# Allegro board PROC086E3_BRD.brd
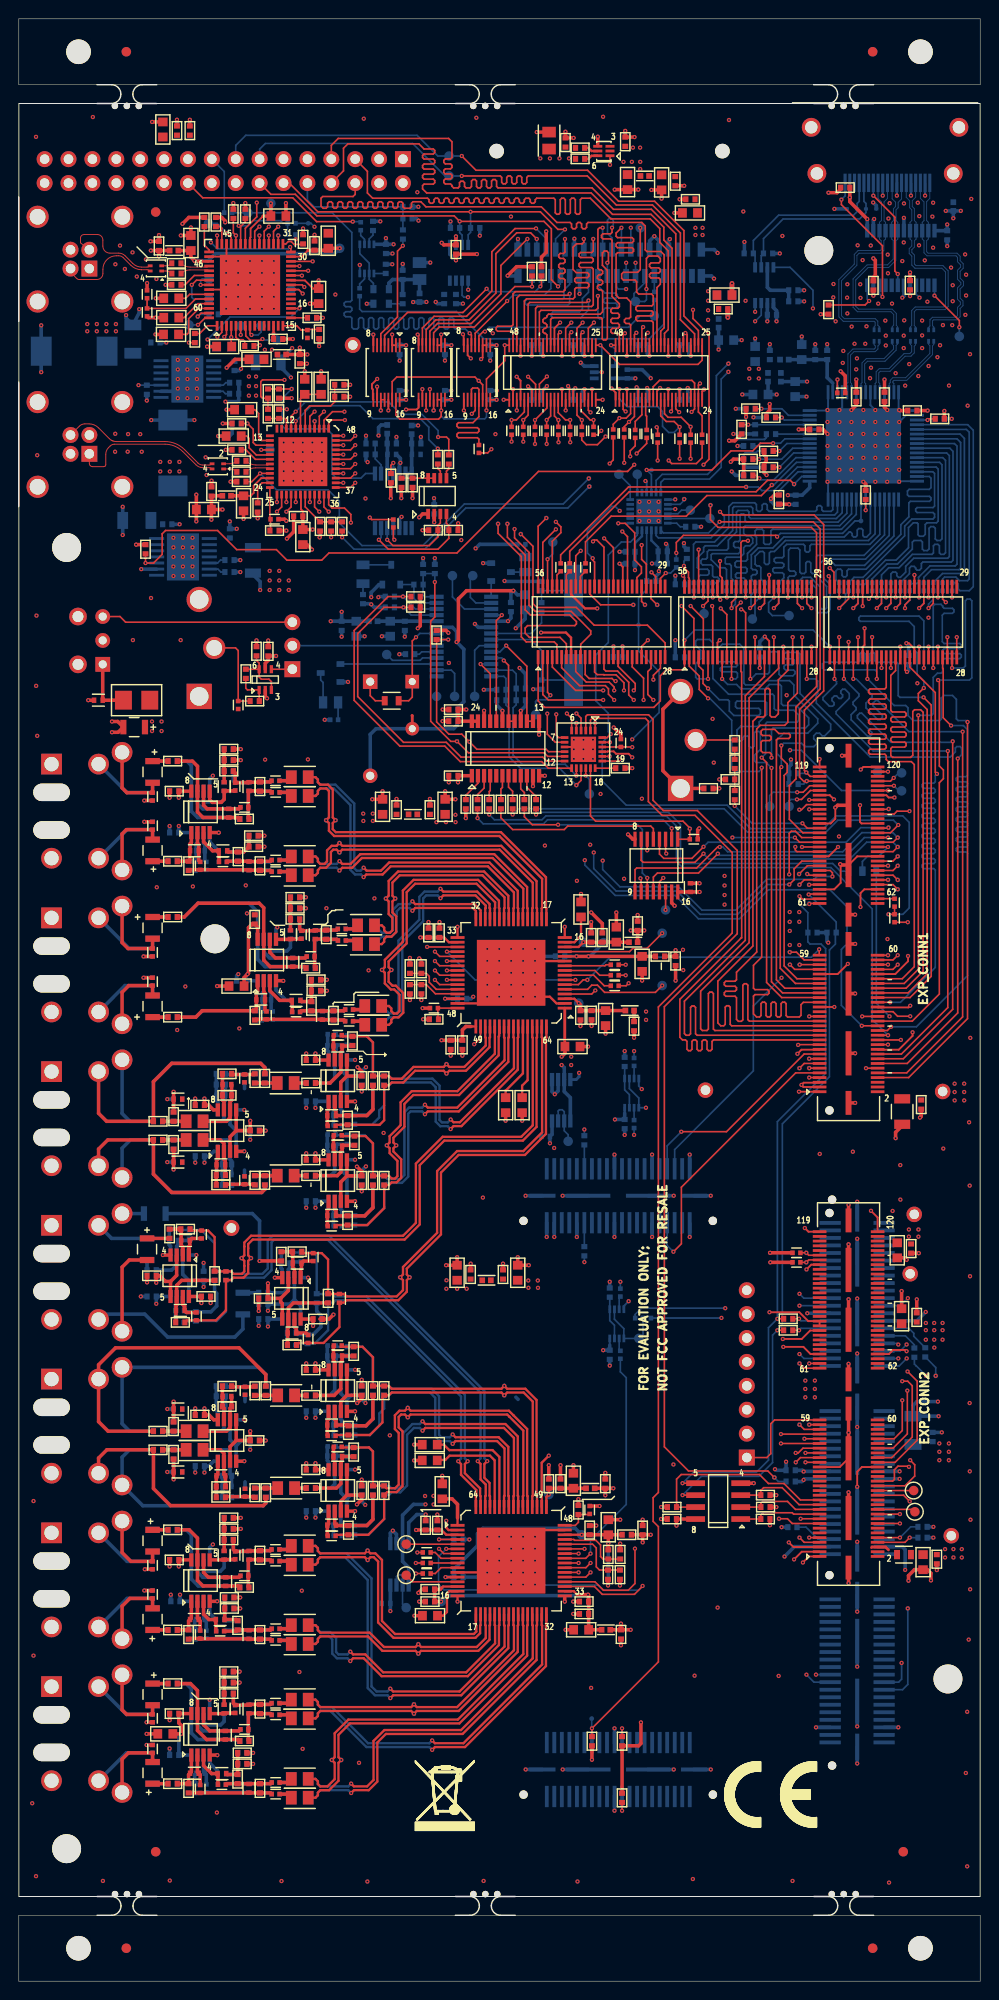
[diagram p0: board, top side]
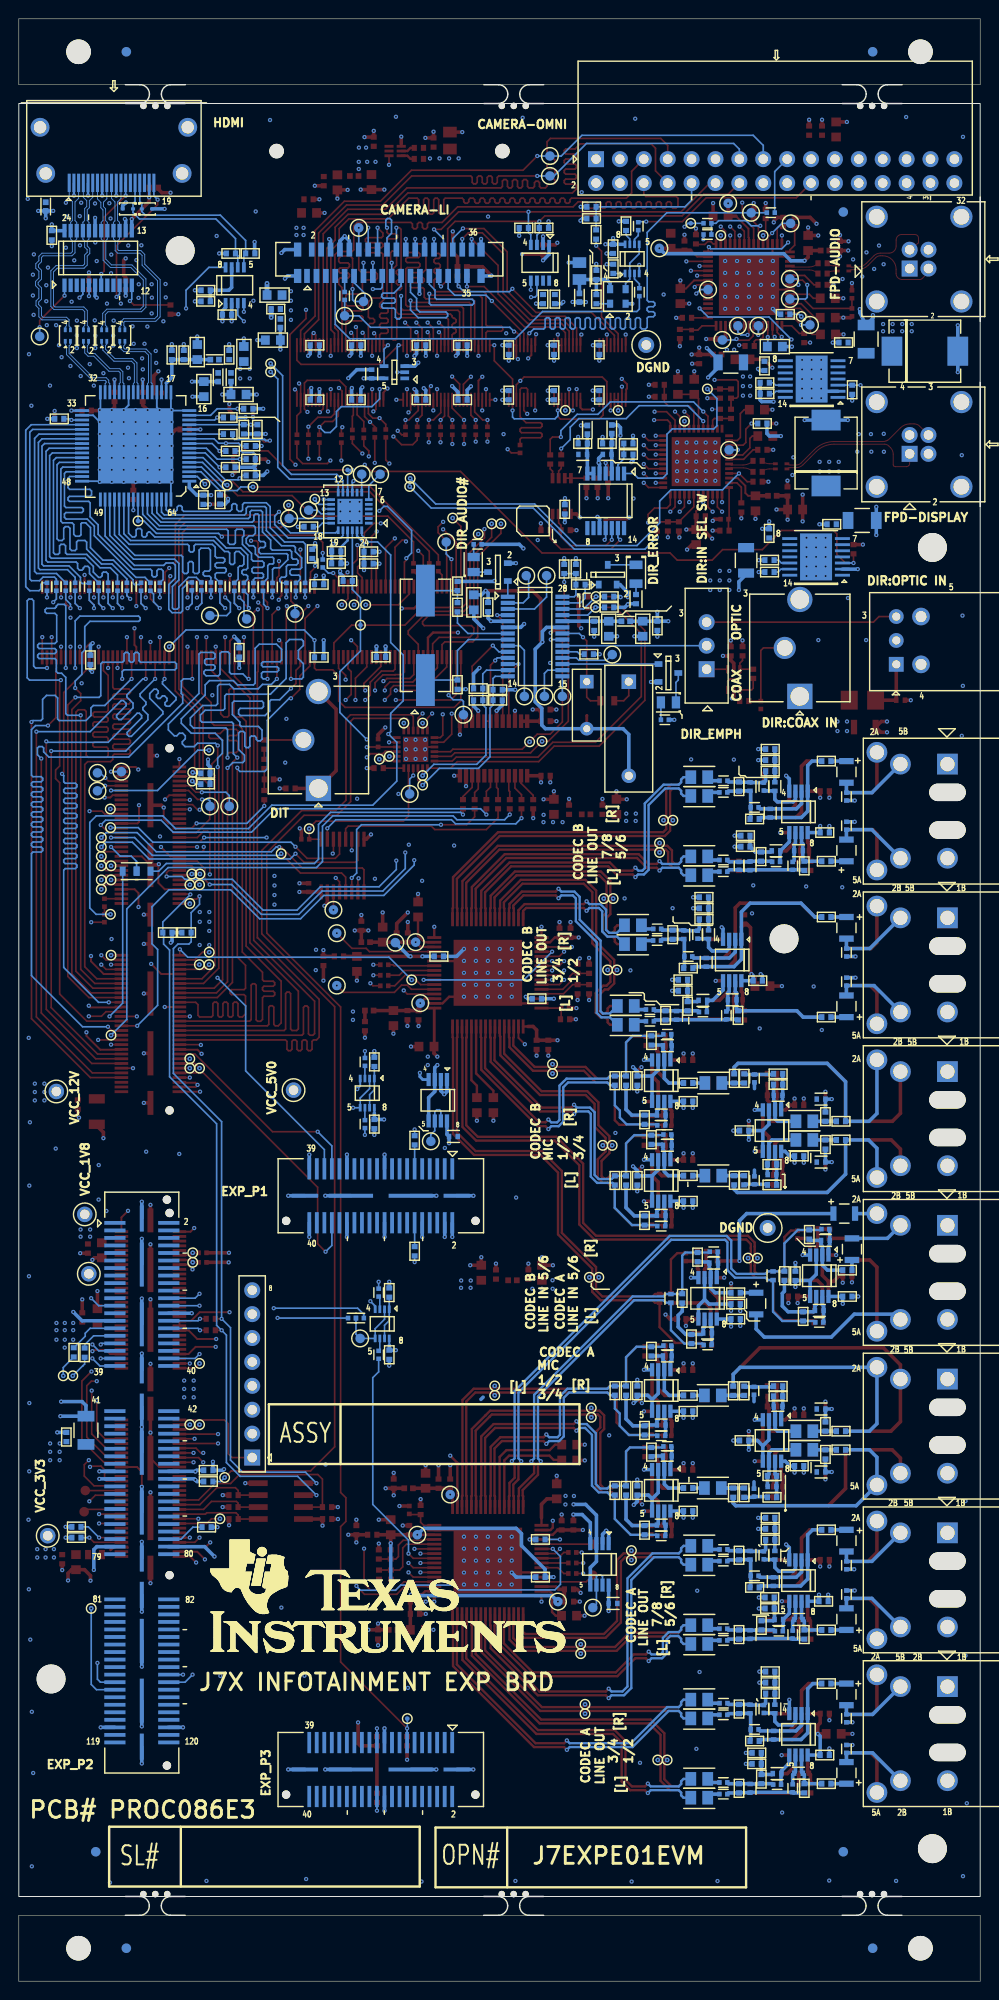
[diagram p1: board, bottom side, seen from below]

Outline 102.21 x 208.5 mm; copper layers: TOP, L02_GND1, L03_SIG1, L04_GND2, L05_PWR1, L06_PWR2, L07_GND3, L08_SIG2, L09_GND4, BOTTOM. Coordinates in mm from the lower left corner of the outline.
Outline path: rectangle 0,9 102.21,199.5 ; 0,208.5 0,201.5 102.21,201.5 102.21,208.5 0,208.5 ; 0,7 0,0 102.21,0 102.21,7 0,7

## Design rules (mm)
net group BUF_VPFE0_DATA0: nets BUF_VPFE0_DATA0 VPFE0_DATA0
net group BUF_VPFE0_DATA1: nets BUF_VPFE0_DATA1 VPFE0_DATA1
net group BUF_VPFE0_DATA2: nets BUF_VPFE0_DATA2 VPFE0_DATA2
net group BUF_VPFE0_DATA3: nets BUF_VPFE0_DATA3 VPFE0_DATA3
net group BUF_VPFE0_DATA4: nets BUF_VPFE0_DATA4 VPFE0_DATA4
net group BUF_VPFE0_DATA5: nets BUF_VPFE0_DATA5 VPFE0_DATA5
net group BUF_VPFE0_DATA6: nets BUF_VPFE0_DATA6 VPFE0_DATA6
net group BUF_VPFE0_DATA7: nets BUF_VPFE0_DATA7 VPFE0_DATA7
net group BUF_VPFE0_DATA8: nets BUF_VPFE0_DATA8 VPFE0_DATA8
net group BUF_VPFE0_DATA9: nets BUF_VPFE0_DATA9 VPFE0_DATA9
net group BUF_VPFE0_DATA10: nets BUF_VPFE0_DATA10 VPFE0_DATA10
net group BUF_VPFE0_DATA11: nets BUF_VPFE0_DATA11 VPFE0_DATA11
net group BUF_VPFE0_DATA12: nets BUF_VPFE0_DATA12 VPFE0_DATA12
net group BUF_VPFE0_DATA13: nets BUF_VPFE0_DATA13 VPFE0_DATA13
net group BUF_VPFE0_HD: nets BUF_VPFE0_HD VPFE0_HD
net group BUF_VPFE0_PCLK: nets BUF_VPFE0_PCLK VPFE0_PCLK
net group BUF_VPFE0_VD: nets BUF_VPFE0_VD VPFE0_VD
net group DIFFPAIR0: nets AOUT2_N AOUT2_P
net group DIFFPAIR1: nets AOUT1_N AOUT1_P
net group DIFFPAIR2: nets AOUT6_N AOUT6_P
net group DIFFPAIR3: nets AOUT5_N AOUT5_P
net group DIFFPAIR4: nets AOUT3_N AOUT3_P
net group DIFFPAIR5: nets AOUT4_N AOUT4_P
net group DIFFPAIR6: nets AOUT7_N AOUT7_P
net group DIFFPAIR7: nets AOUT8_N AOUT8_P
net group DIFFPAIR8: nets AIN4_N AIN4_P
net group DIFFPAIR9: nets AIN3_N AIN3_P
net group DIFFPAIR10: nets AIN2_N AIN2_P
net group DIFFPAIR11: nets AIN1_N AIN1_P
net group DIFFPAIR12: nets AIN6_N AIN6_P
net group DIFFPAIR14: nets AIN5_N AIN5_P
net group DIFFPAIR15: nets BOUT2_N BOUT2_P
net group DIFFPAIR16: nets BOUT1_N BOUT1_P
net group DIFFPAIR17: nets BOUT6_N BOUT6_P
net group DIFFPAIR18: nets BOUT5_N BOUT5_P
net group DIFFPAIR19: nets BOUT3_N BOUT3_P
net group DIFFPAIR20: nets BOUT4_N BOUT4_P
net group DIFFPAIR21: nets BOUT7_N BOUT7_P
net group DIFFPAIR22: nets BOUT8_N BOUT8_P
net group DIFFPAIR24: nets BIN1_N BIN1_P
net group DIFFPAIR25: nets BIN2_N BIN2_P
net group DIFFPAIR27: nets BIN4_N BIN4_P
net group DIFFPAIR36: nets C_FPD_RIN_N C_FPD_RIN_P
net group DIFFPAIR37: nets CMC_FPD_RIN_N CMC_FPD_RIN_P
net group DIFFPAIR38: nets FPD_RIN_N FPD_RIN_P
net group DIFFPAIR39: nets C_FPD_DOUT_N C_FPD_DOUT_P
net group DIFFPAIR40: nets CMC_FPD_DOUT_N CMC_FPD_DOUT_P
net group DIFFPAIR41: nets FPD_DOUT_N FPD_DOUT_P
net group DIFFPAIR45: nets BIN6_N BIN6_P
net group DIFFPAIR46: nets BIN5_N BIN5_P
net group DIFFPAIR47: nets BIN3_N BIN3_P
net group HDMI1_DATA0: nets HDMI1_DATA0 HDMI1_DATA0_R
net group HDMI1_DATA1: nets HDMI1_DATA1 HDMI1_DATA1_R
net group HDMI1_DATA2: nets HDMI1_DATA2 HDMI1_DATA2_R
net group HDMI1_DATA3: nets HDMI1_DATA3 HDMI1_DATA3_R
net group HDMI1_DATA4: nets HDMI1_DATA4 HDMI1_DATA4_R
net group HDMI1_DATA5: nets HDMI1_DATA5 HDMI1_DATA5_R
net group HDMI1_DATA6: nets HDMI1_DATA6 HDMI1_DATA6_R
net group HDMI1_DATA7: nets HDMI1_DATA7 HDMI1_DATA7_R
net group HDMI1_DATA8: nets HDMI1_DATA8 HDMI1_DATA8_R
net group HDMI1_DATA9: nets HDMI1_DATA9 HDMI1_DATA9_R
net group HDMI1_DATA10: nets HDMI1_DATA10 HDMI1_DATA10_R
net group HDMI1_DATA11: nets HDMI1_DATA11 HDMI1_DATA11_R
net group HDMI1_DATA12: nets HDMI1_DATA12 HDMI1_DATA12_R
net group HDMI1_DATA13: nets HDMI1_DATA13 HDMI1_DATA13_R
net group HDMI1_DATA14: nets HDMI1_DATA14 HDMI1_DATA14_R
net group HDMI1_DATA15: nets HDMI1_DATA15 HDMI1_DATA15_R
net group HDMI1_DATA16: nets HDMI1_DATA16 HDMI1_DATA16_R
net group HDMI1_DATA17: nets HDMI1_DATA17 HDMI1_DATA17_R
net group HDMI1_DATA18: nets HDMI1_DATA18 HDMI1_DATA18_R
net group HDMI1_DATA19: nets HDMI1_DATA19 HDMI1_DATA19_R
net group HDMI1_DATA20: nets HDMI1_DATA20 HDMI1_DATA20_R
net group HDMI1_DATA21: nets HDMI1_DATA21 HDMI1_DATA21_R
net group HDMI1_DATA22: nets HDMI1_DATA22 HDMI1_DATA22_R
net group HDMI1_DATA23: nets HDMI1_DATA23 HDMI1_DATA23_R
net group HDMI1_DE: nets HDMI1_DE HDMI1_DE_R
net group HDMI1_HSYNC: nets HDMI1_HSYNC HDMI1_HSYNC_R
net group HDMI1_PCLK: nets HDMI1_PCLK HDMI1_PCLK_R
net group HDMI1_VSYNC: nets HDMI1_VSYNC HDMI1_VSYNC_R
net group LI_VIN_PCLK: nets LI_VIN_PCLK R_LI_VIN_PCLK
net group MCASP0_AXR12: nets MCASP0_AXR12 MCASP0_AXR12_R
net group MCASP0_AXR13: nets MCASP0_AXR13 MCASP0_AXR13_R
net group OV_VIN_PCLK_R: nets OV_VIN_PCLK OV_VIN_PCLK_R
net group CAMERA: nets LI_VIN_DATA3 LI_VIN_DATA4 LI_VIN_DATA5 LI_VIN_DATA6 LI_VIN_DATA7 LI_VIN_DATA8 LI_VIN_DATA9 LI_VIN_DATA10 LI_VIN_DATA11 LI_VIN_DATA12 LI_VIN_DATA13
net group MCASP0-GP1: nets MCASP0_AXR7 MCASP0_AXR8 MCASP0_AXR9
net group MCASP0_AXR4: nets MCASP0_AXR4_R
net group MCASP0_AXR5: nets MCASP0_AXR5_R
net group MCASP0_AXR6: nets MCASP0_AXR6_R
net group MCASP0_AXR11: nets MCASP0_AXR11
net group MCASP1: nets MCASP1_ACLKX MCASP1_AFSX MCASP1_AXR0 MCASP1_AXR1 MCASP1_AXR2 MCASP1_AXR3 MCASP1_AXR5 MCASP1_AXR7 MCASP1_AXR8
net group OV_VIN_D0-D11: nets OV_VIN_VD
net group PCLK_R: nets FPD_PCLK
net group POWER: nets DIT_GND N24788879 V3V3_OPTICAL V5V0_HDMI1_CONN V_PVDD VCC_CAM_OSC VCC_DIR VCOMDA1 VCOMDA2 VDD33_FPD VDD33_UB926 VDD_CDCE VDDOUT_CDCE VLDO_CAM_1V8 VLDO_CAM_3V3
net group VOUT0_DATA0_M1: nets VOUT0_DE VOUT0_HSYNC VOUT0_VSYNC

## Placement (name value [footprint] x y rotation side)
C1  2.2uF  [CAP0805_1-5]  56.38 195.56 90 top
C2  1uF  [CAP0402_0-5]  64.47 195.44 90 top
C3  10uF  [CAP0603_1]  68.34 191.12 270 top
C4  10uF  [CAP0603_1]  64.72 191.16 270 top
C5  0.1uF  [CAP0402_0-75]  69.79 191.25 270 top
C6  0.1uF  [CAP0402_0-75]  87.86 190.57 180 top
C7  0.1uF  [CAP0402_0-75]  71.4 189.33 180 top
C8  0.1uF  [CAP0402_0-75]  27.57 174.48 0 top
C9  4.7uF  [CAP0603_1]  27.6 187.54 0 top
C10  10uF  [CAP0603_1]  71.35 187.88 180 top
C11  4.7uF  [CAP0603_1]  32.9 184.92 90 top
C12  4.7uF  [CAP0603_1]  18.3 184.68 90 top
C13  0.1uF  [CAP0402_0-75]  31.44 184.41 90 top
C14  0.1uF  [CAP0402_0-75]  14.91 184.37 90 top
C15  0.1uF  [CAP0402_0-75]  46.48 183.99 270 top
C16  0.1uF  [CAP0402_0-75]  16.75 182.53 180 top
C17  0.1uF  [CAP0402_0-75]  16.76 181.44 180 top
C18  0.1uF  [CAP0402_0-75]  16.76 180.24 180 top
C19  10uF  [CAP0603_1]  75.02 179.15 0 top
C20  4.7uF  [CAP0603_1]  31.88 179.04 270 top
C21  4.7uF  [CAP0603_1]  16.21 178.81 180 top
C22  0.1uF  [CAP0402_0-75]  74.89 177.66 0 top
C23  4.7uF  [CAP0603_1]  16.21 176.75 180 top
C24  4.7uF  [CAP0603_1]  16.18 174.97 180 top
C25  4.7uF  [CAP0603_1]  25.27 172.32 180 top
C26  4.7uF  [CAP0603_1]  21.83 173.68 180 top
C27  0.1uF  [CAP0402_0-75]  29.88 172.35 270 top
C28  4.7uF  [CAP0603_1]  30.4 169.4 90 top
C29  4.7uF  [CAP0603_1]  32.14 169.4 90 top
C30  0.1uF  [CAP0402_0-75]  89.04 168.33 270 top
C31  0.1uF  [CAP0402_0-75]  92.04 168.33 270 top
C32  4.7uF  [CAP0603_1]  23.74 166.97 180 top
C33  0.1uF  [CAP0402_0-75]  95 166.87 180 top
C34  0.1uF  [CAP0402_0-75]  84.58 164.87 0 top
C35  4.7uF  [CAP0603_1]  22.85 164.17 180 top
C36  0.1uF  [CAP0402_0-75]  23.66 161.53 180 top
C37  0.1uF  [CAP0402_0-75]  23.66 160.37 180 top
C38  0.1uF  [CAP0402_0-75]  41.86 159.2 270 top
C39  10uF  [CAP0603_1]  19.68 156.36 180 top
C40  0.1uF  [CAP0402_0-75]  20.49 158.28 90 top
C41  10uF  [CAP0603_1]  23.89 157.02 270 top
C42  0.1uF  [CAP0402_0-75]  25.4 156.58 90 top
C43  0.1uF  [CAP0402_0-75]  29.71 155.65 180 top
C44  10uF  [CAP0603_1]  30.2 153.44 270 top
C45  0.1uF  [CAP0402_0-75]  26.52 141.3 90 top
C46  0.1uF  [CAP0402_0-75]  8.46 136.1 180 top
C47  0.1uF  [CAP0402_0-75]  25.08 136.01 180 top
C48  0.1uF  [CAP0402_0-75]  46.21 135.11 180 top
C49  0.1uF  [CAP0402_0-75]  46.2 133.88 180 top
C50  10uF_10V  [CAPCT0805H_1]  12.26 133.25 180 top
C51  0.1uF  [CAP0402_0-75]  76.11 129.33 90 top
C52  10uF_10V  [CAPCT0805H_1]  14.22 128.48 270 top
C53  680pF  [CAP0402_0-75]  22.32 124.1 270 top
C54  0.1uF  [CAP0402_0-75]  46.2 128.08 180 top
C55  10uF  [CAP0805_1-5]  29.87 127.93 0 top
C56  680pF  [CAP0402_0-75]  21.83 126.93 90 top
C57  3300pF  [CAP0402_0-75]  24.47 126.93 90 top
C58  0.1uF  [CAP0402_0-75]  16.52 126.44 180 top
C59  10uF  [CAP0805_1-5]  29.87 125.93 0 top
C60  10uF  [CAP0603_1]  38.67 124.78 90 top
C61  10uF  [CAP0603_1]  45.32 124.78 90 top
C62  0.1uF  [CAP0402_0-75]  40.16 124.47 90 top
C63  0.1uF  [CAP0402_0-75]  43.71 124.47 90 top
C64  10uF_10V  [CAPCT0805H_1]  14.22 120.14 90 top
C65  680pF  [CAP0402_0-75]  18.67 120.11 180 top
C66  10uF  [CAP0805_1-5]  29.87 119.5 0 top
C67  680pF  [CAP0402_0-75]  21.7 120.1 0 top
C68  3300pF  [CAP0402_0-75]  24.47 118.5 90 top
C69  10uF  [CAP0805_1-5]  29.87 117.51 0 top
C70  0.1uF  [CAP0402_0-75]  71.4 116.19 90 top
C71  680pF  [CAP0402_0-75]  29.13 108.25 270 top
C72  10uF_10V  [CAPCT0805H_1]  14.22 111.92 270 top
C73  10uF  [CAP0805_1-5]  36.92 112.19 0 top
C74  10uF  [CAP0603_1]  59.77 113.87 90 top
C75  680pF  [CAP0402_0-75]  28.88 111.19 90 top
C76  3300pF  [CAP0402_0-75]  31.52 111.19 90 top
C77  0.1uF  [CAP0402_0-75]  65.79 112.13 90 top
C78  0.1uF  [CAP0402_0-75]  25.08 112.81 90 top
C79  0.1uF  [CAP0402_0-75]  43.56 111.38 90 top
C80  1uF  [CAP0402_0-5]  44.72 111.38 90 top
C81  10uF  [CAP0805_1-5]  36.92 110.19 0 top
C82  10uF  [CAP0603_1]  63.53 111.19 90 top
C83  0.1uF  [CAP0402_0-75]  60.85 110.88 90 top
C84  1uF  [CAP0402_0-5]  62.03 110.88 90 top
C85  10uF  [CAP0603_1]  23.15 105.73 180 top
C86  0.1uF  [CAP0402_0-75]  69.83 108.4 270 top
C87  10uF  [CAP0603_1]  66.27 108.09 270 top
C88  680pF  [CAP0402_0-75]  25.72 104.27 180 top
C89  10uF_10V  [CAPCT0805H_1]  14.22 103.58 90 top
C90  10uF  [CAP0805_1-5]  37.68 103.61 0 top
C91  680pF  [CAP0402_0-75]  29.48 104.21 0 top
C92  3300pF  [CAP0402_0-75]  32.28 102.61 90 top
C93  1uF  [CAP0402_0-5]  60.89 102.64 270 top
C94  1uF  [CAP0402_0-5]  59.71 102.63 270 top
C95  10uF  [CAP0603_1]  62.38 102.33 270 top
C96  10uF  [CAP0805_1-5]  37.68 101.62 0 top
C97  0.1uF  [CAP0402_0-75]  65.41 101.47 270 top
C98  2200pF  [CAP0402_0-75]  33.91 99.36 180 top
C99  0.1uF  [CAP0402_0-75]  31.05 97.87 180 top
C100  10uF  [CAP0603_1]  58.87 99.3 0 top
C101  0.1uF  [CAP0402_0-75]  45.92 99.48 270 top
C102  0.1uF  [CAP0402_0-75]  47.16 99.48 270 top
C103  0.1uF  [CAP0402_0-75]  36.46 95.68 270 top
C104  0.1uF  [CAP0402_0-75]  38.84 95.68 90 top
C105  10uF  [CAP0805_1-5]  28.37 95.43 180 top
C106  3.3pF  [CAP0402_0-75]  22.13 95.26 180 top
C107  0.1uF  [CAP0402_0-75]  19.25 93.08 180 top
C108  22pF  [CAP0402_0-75]  33.26 91.97 180 top
C109  0.1uF  [CAP0402_0-75]  64.41 91.06 270 bottom
C110  0.1uF  [CAP0402_0-75]  95.94 93.14 270 top
C111  2.2uF  [CAP0805_1-5]  18.69 91.36 180 top
C112  10uF  [CAP1206_2]  93.92 92.4 270 top
C113  0.1uF  [CAP0402_0-75]  25.09 90.37 0 top
C114  2.2uF  [CAP0805_1-5]  18.69 89.38 180 top
C115  2200pF  [CAP0402_0-75]  33.91 88.73 180 top
C116  0.1uF  [CAP0402_0-75]  31.05 87.26 180 top
C117  3.3pF  [CAP0402_0-75]  21.48 86.74 180 top
C118  10uF  [CAP0805_1-5]  28.37 85.58 180 top
C119  0.1uF  [CAP0402_0-75]  36.46 85.08 270 top
C120  0.1uF  [CAP0402_0-75]  38.84 85.08 90 top
C121  22pF  [CAP0402_0-75]  33.26 81.36 180 top
C122  10uF_10V  [CAPCT0805H_1]  14.45 81.56 180 bottom
C123  2200pF  [CAP0402_0-75]  29.59 76.3 0 top
C124  0.1uF  [CAP0402_0-75]  14.12 74.95 180 top
C125  0.01uF  [CAP0402_0-75]  34.09 72.55 270 top
C126  0.1uF  [CAP0402_0-75]  14.12 72.75 180 bottom
C127  0.1uF  [CAP0402_0-75]  94.86 77.84 270 top
C128  10uF  [CAP0603_1]  93.39 77.66 270 top
C129  22pF  [CAP0402_0-75]  29.04 68.87 0 top
C130  10uF  [CAP0603_1]  46.6 75.27 90 top
C131  10uF  [CAP0603_1]  53.04 75.27 90 top
C132  0.1uF  [CAP0402_0-75]  48.03 75.09 90 top
C133  0.1uF  [CAP0402_0-75]  51.48 75.09 90 top
C134  10uF_10V  [CAPCT0805H_1]  23.82 72 270 bottom
C135  2200pF  [CAP0402_0-75]  28.33 76.3 180 bottom
C136  0.1uF  [CAP0402_0-75]  62.83 66.55 270 bottom
C137  10uF  [CAP0603_1]  93.85 70.65 90 top
C138  0.1uF  [CAP0402_0-75]  95.47 70.53 90 top
C139  0.1uF  [CAP0402_0-75]  26 71.94 180 bottom
C140  0.01uF  [CAP0402_0-75]  32.88 72.55 270 bottom
C141  0.1uF  [CAP0402_0-75]  26 70.35 180 bottom
C142  22pF  [CAP0402_0-75]  28.98 68.87 180 bottom
C143  2200pF  [CAP0402_0-75]  33.91 66.43 180 top
C144  0.1uF  [CAP0402_0-75]  31.05 64.94 180 top
C145  0.1uF  [CAP0402_0-75]  36.46 62.74 90 top
C146  0.1uF  [CAP0402_0-75]  38.84 62.74 90 top
C147  10uF  [CAP0805_1-5]  28.42 62.24 180 top
C148  3.3pF  [CAP0402_0-75]  22.13 62.12 180 top
C149  0.1uF  [CAP0402_0-75]  19.25 60.16 180 top
C150  22pF  [CAP0402_0-75]  33.26 59.09 180 top
C151  2.2uF  [CAP0805_1-5]  18.69 58.44 180 top
C152  0.1uF  [CAP0402_0-75]  25.09 57.45 0 top
C153  2.2uF  [CAP0805_1-5]  18.69 56.46 180 top
C154  2200pF  [CAP0402_0-75]  33.91 55.75 180 top
C155  0.1uF  [CAP0402_0-75]  31.05 54.34 180 top
C156  3.3pF  [CAP0402_0-75]  21.48 53.7 180 top
C157  10uF  [CAP0603_1]  43.69 57.01 180 top
C158  10uF  [CAP0805_1-5]  28.42 52.39 180 top
C159  0.1uF  [CAP0402_0-75]  36.46 52.14 90 top
C160  0.1uF  [CAP0402_0-75]  38.84 52.14 90 top
C161  10uF  [CAP0603_1]  43.69 55.33 180 top
C162  0.1uF  [CAP0402_0-75]  69.43 49.1 180 top
C163  22pF  [CAP0402_0-75]  33.26 48.46 180 top
C164  10uF  [CAP0603_1]  58.96 53.17 90 top
C165  0.1uF  [CAP0402_0-75]  56.35 52.86 90 top
C166  0.1uF  [CAP0402_0-75]  57.59 52.86 90 top
C167  0.1uF  [CAP0402_0-75]  62.35 52.86 90 top
C168  10uF_10V  [CAPCT0805H_1]  14.22 46.81 270 top
C169  680pF  [CAP0402_0-75]  21.99 42.45 270 top
C170  10uF  [CAP0805_1-5]  29.87 46.25 0 top
C171  10uF  [CAP0603_1]  45.02 52.05 90 top
C172  680pF  [CAP0402_0-75]  21.83 45.25 90 top
C173  3300pF  [CAP0402_0-75]  24.47 45.25 90 top
C174  0.1uF  [CAP0402_0-75]  97.6 44.83 270 top
C175  0.1uF  [CAP0402_0-75]  16.52 44.76 180 top
C176  10uF  [CAP0603_1]  96.13 44.52 270 top
C177  10uF  [CAP0805_1-5]  29.87 44.25 0 top
C178  1uF  [CAP0402_0-5]  43.25 48.43 90 top
C179  1uF  [CAP0402_0-5]  44.5 48.43 90 top
C180  10uF  [CAP0603_1]  62.67 48.23 90 top
C181  0.1uF  [CAP0402_0-75]  60.69 47.92 90 top
C182  0.1uF  [CAP0402_0-75]  66.32 47.92 90 top
C183  10uF_10V  [CAPCT0805H_1]  14.22 38.47 90 top
C184  680pF  [CAP0402_0-75]  18.67 38.43 180 top
C185  10uF  [CAP0805_1-5]  29.87 37.83 0 top
C186  680pF  [CAP0402_0-75]  21.4 38.42 0 top
C187  3300pF  [CAP0402_0-75]  24.47 36.83 90 top
C188  1uF  [CAP0402_0-5]  43.71 41.64 180 top
C189  10uF  [CAP0805_1-5]  29.87 35.83 0 top
C190  0.1uF  [CAP0402_0-75]  43.71 40.33 180 top
C191  0.1uF  [CAP0402_0-75]  60.09 40.33 180 top
C192  1uF  [CAP0402_0-5]  60.09 39.02 180 top
C193  10uF  [CAP0603_1]  43.71 38.83 180 top
C194  10uF  [CAP0603_1]  59.78 37.33 180 top
C195  0.1uF  [CAP0402_0-75]  64.02 36.84 270 top
C196  10uF_10V  [CAPCT0805H_1]  14.22 30.47 270 top
C197  680pF  [CAP0402_0-75]  21.96 26.13 270 top
C198  10uF  [CAP0805_1-5]  29.87 29.91 0 top
C199  680pF  [CAP0402_0-75]  21.83 28.92 90 top
C200  3300pF  [CAP0402_0-75]  24.47 28.92 90 top
C201  0.1uF  [CAP0402_0-75]  16.52 28.43 180 top
C202  10uF  [CAP0805_1-5]  29.87 27.92 0 top
C203  10uF  [CAP0603_1]  15.58 26.28 180 top
C204  10uF_10V  [CAPCT0805H_1]  14.22 22.13 90 top
C205  680pF  [CAP0402_0-75]  18.67 22.1 180 top
C206  10uF  [CAP0805_1-5]  29.87 21.49 0 top
C207  680pF  [CAP0402_0-75]  21.59 22.06 0 top
C208  3300pF  [CAP0402_0-75]  24.47 20.49 90 top
C209  10uF  [CAP0805_1-5]  29.87 19.49 0 top
C210  0.1uF  [CAP0402_0-75]  18.19 196.62 90 top
C211  0.1uF  [CAP0402_0-75]  16.81 196.62 90 top
C212  10uF  [CAP0603_1]  15.32 196.74 90 top
C213  0.1uF  [CAP0402_0-75]  98.7 185.5 270 bottom
C214  0.1uF  [CAP0402_0-75]  39.03 184.05 270 bottom
C215  2.2uF  [CAP0805_1-5]  42.61 181.7 90 bottom
C216  0.1uF  [CAP0402_0-75]  40.81 181.29 90 bottom
C217  0.1uF  [CAP0402_0-75]  82.34 179.66 0 bottom
C218  10uF  [CAP0603_1]  75.02 179.15 0 bottom
C219  0.1uF  [CAP0402_0-75]  45.22 178.72 270 bottom
C220  0.1uF  [CAP0402_0-75]  90.85 180.17 90 top
C221  0.1uF  [CAP0402_0-75]  74.89 177.66 0 bottom
C222  0.1uF  [CAP0402_0-75]  80.07 177.06 0 bottom
C223  22uF  [CAP1206_2#2]  12.13 174.47 90 bottom
C224  10uF  [CAP0603_1]  75.2 174.36 0 bottom
C225  0.1uF  [CAP0402_0-75]  70.74 173.82 0 bottom
C226  0.1uF  [CAP0402_0-75]  66.34 173.82 0 bottom
C227  0.1uF  [CAP0402_0-75]  59.43 173.82 0 bottom
C228  0.1uF  [CAP0402_0-75]  55.03 173.82 0 bottom
C229  4.7uF  [CAP0603_1]  21.83 173.68 180 bottom
C230  0.1uF  [CAP0402_0-75]  14.53 174.11 180 bottom
C231  0.1uF  [CAP0402_0-75]  50.12 173.33 270 bottom
C232  0.1uF  [CAP0402_0-75]  45.3 173.33 270 bottom
C233  0.1uF  [CAP0402_0-75]  40.49 173.33 270 bottom
C234  10uF  [CAP0603_1]  78.28 172.88 90 bottom
C235  10uF  [CAP0603_1]  83.24 173.09 90 bottom
C236  0.1uF  [CAP0402_0-75]  79.85 172.78 90 bottom
C237  0.1uF  [CAP0402_0-75]  85.94 172.78 90 bottom
C238  0.1uF  [CAP0402_0-75]  84.67 172.78 90 bottom
C239  10uF  [CAP1206_2]  26.52 172 0 bottom
C240  0.1uF  [CAP0402_0-75]  22.93 171.62 270 bottom
C241  0.1uF  [CAP0402_0-75]  64.69 170.76 90 bottom
C242  10uF  [CAP0603_1]  82.54 169.16 270 bottom
C243  10uF  [CAP0603_1]  78.85 168.58 180 bottom
C244  0.1uF  [CAP0402_0-75]  50.12 168.51 270 bottom
C245  0.1uF  [CAP0402_0-75]  45.3 168.51 270 bottom
C246  0.1uF  [CAP0402_0-75]  40.49 168.51 270 bottom
C247  0.1uF  [CAP0402_0-75]  70.74 168.02 0 bottom
C248  0.1uF  [CAP0402_0-75]  66.34 168.02 180 bottom
C249  0.1uF  [CAP0402_0-75]  59.43 168.02 0 bottom
C250  0.1uF  [CAP0402_0-75]  55.03 168.02 180 bottom
C251  1uF  [CAP0402_0-5]  78.28 164.88 270 bottom
C252  0.1uF  [CAP0402_0-75]  42.26 163.38 0 bottom
C253  0.1uF  [CAP0402_0-75]  39.66 163.38 0 bottom
C254  0.01uF  [CAP0402_0-75]  42.26 162.22 0 bottom
C255  0.01uF  [CAP0402_0-75]  39.66 162.22 0 bottom
C256  0.1uF  [CAP0402_0-75]  82.6 157.4 270 bottom
C257  22uF  [CAP1206_2#2]  12.55 155.2 180 bottom
C258  0.1uF  [CAP0402_0-75]  44.16 156.38 90 bottom
C259  0.1uF  [CAP0402_0-75]  15.79 154.8 180 bottom
C260  0.1uF  [CAP0402_0-75]  22.43 153.83 90 bottom
C261  0.1uF  [CAP0402_0-75]  63.7 140.68 0 bottom
C262  0.1uF  [CAP0402_0-75]  68.46 151.92 0 bottom
C263  0.1uF  [CAP0402_0-75]  65.02 151.88 180 bottom
C264  10uF  [CAP1206_2]  24.89 150.96 270 bottom
C265  0.1uF  [CAP0402_0-75]  68.46 150.63 0 bottom
C266  0.1uF  [CAP0402_0-75]  65.02 150.61 180 bottom
C267  27pF  [CAP0402_0-75]  55.58 148.24 90 bottom
C268  10uF  [CAP0603_1]  53.83 146.5 90 bottom
C269  0.1uF  [CAP0402_0-75]  52.32 146 90 bottom
C270  0.1uF  [CAP0402_0-75]  41.04 144 270 bottom
C271  0.1uF  [CAP0402_0-75]  34.32 144 270 bottom
C272  10uF  [CAP0603_1]  39.49 143.69 270 bottom
C273  10uF  [CAP0603_1]  35.87 143.69 270 bottom
C274  0.1uF  [CAP0402_0-75]  78.78 141.17 90 bottom
C275  0.1uF  [CAP0402_0-75]  94.6 140.39 90 bottom
C276  27pF  [CAP0402_0-75]  55.58 137.76 270 bottom
C277  4700pF_100V  [CAP_196-85_280X100_TH_6-5]  41.83 138.08 270 bottom
C278  0.068uF_300V  [CAP_393-7_510X180_TH_10-5]  37.36 138.08 270 bottom
C279  10uF_10V  [CAPCT0805H_1]  14.22 128.48 270 bottom
C280  680pF  [CAP0402_0-75]  22.32 124.1 270 bottom
C281  10uF  [CAP0805_1-5]  29.87 127.93 0 bottom
C282  3300pF  [CAP0402_0-75]  24.47 126.93 90 bottom
C283  680pF  [CAP0402_0-75]  21.83 126.93 90 bottom
C284  10uF  [CAP0805_1-5]  29.87 125.93 0 bottom
C285  0.1uF  [CAP0402_0-75]  16.52 122.04 180 bottom
C286  10uF_10V  [CAPCT0805H_1]  14.22 120.14 90 bottom
C287  680pF  [CAP0402_0-75]  19.32 120.11 180 bottom
C288  10uF  [CAP0805_1-5]  29.87 119.5 0 bottom
C289  3300pF  [CAP0402_0-75]  24.47 118.5 90 bottom
C290  680pF  [CAP0402_0-75]  21.7 120.1 0 bottom
C291  10uF  [CAP0805_1-5]  29.87 117.51 0 bottom
C292  680pF  [CAP0402_0-75]  29.13 108.25 270 bottom
C293  10uF_10V  [CAPCT0805H_1]  14.22 111.92 270 bottom
C294  10uF  [CAP0805_1-5]  36.92 112.19 0 bottom
C295  3300pF  [CAP0402_0-75]  31.52 111.19 90 bottom
C296  680pF  [CAP0402_0-75]  28.88 111.19 90 bottom
C297  10uF  [CAP0805_1-5]  36.92 110.19 0 bottom
C298  0.1uF  [CAP0402_0-75]  57.55 108.89 180 bottom
C299  0.1uF  [CAP0402_0-75]  23.65 106.3 180 bottom
C300  680pF  [CAP0402_0-75]  26.37 104.27 180 bottom
C301  10uF_10V  [CAPCT0805H_1]  14.22 103.58 90 bottom
C302  10uF  [CAP0805_1-5]  37.68 103.61 0 bottom
C303  0.1uF  [CAP0402_0-75]  47.13 104.39 0 bottom
C304  3300pF  [CAP0402_0-75]  32.28 102.61 90 bottom
C305  680pF  [CAP0402_0-75]  29.48 104.21 0 bottom
C306  10uF  [CAP0805_1-5]  37.68 101.62 0 bottom
C307  2200pF  [CAP0402_0-75]  33.26 99.39 180 bottom
C308  0.1uF  [CAP0402_0-75]  38.84 95.68 90 bottom
C309  0.1uF  [CAP0402_0-75]  36.46 95.68 270 bottom
C310  10uF  [CAP0805_1-5]  28.37 95.43 180 bottom
C311  10uF  [CAP0603_1]  53.51 93.08 270 top
C312  10uF  [CAP0603_1]  51.76 93.08 270 top
C313  3.3pF  [CAP0402_0-75]  21.48 94.12 180 bottom
C314  0.1uF  [CAP0402_0-75]  31.05 93.48 180 bottom
C315  22pF  [CAP0402_0-75]  33.91 92.03 180 bottom
C316  2.2uF  [CAP0805_1-5]  18.69 91.36 180 bottom
C317  0.1uF  [CAP0402_0-75]  25.09 90.37 0 bottom
C318  2.2uF  [CAP0805_1-5]  18.69 89.38 180 bottom
C319  2200pF  [CAP0402_0-75]  33.26 88.81 180 bottom
C320  0.1uF  [CAP0402_0-75]  19.25 87.66 180 bottom
C321  3.3pF  [CAP0402_0-75]  22.13 85.7 180 bottom
C322  10uF  [CAP0805_1-5]  28.37 85.58 180 bottom
C323  0.1uF  [CAP0402_0-75]  38.84 85.08 90 bottom
C324  0.1uF  [CAP0402_0-75]  36.46 85.08 270 bottom
C325  0.1uF  [CAP0402_0-75]  31.05 82.88 180 bottom
C326  22pF  [CAP0402_0-75]  33.91 81.36 180 bottom
C327  22pF  [CAP0402_0-75]  17.11 71.27 180 bottom
C328  0.1uF  [CAP0402_0-75]  31.78 70.35 0 top
C329  0.01uF  [CAP0402_0-75]  22.02 74.95 270 bottom
C330  0.1uF  [CAP0402_0-75]  19.65 74.94 90 bottom
C331  2200pF  [CAP0402_0-75]  16.46 78.7 180 bottom
C332  10uF_10V  [CAPCT0805H_1]  13.63 77.77 90 bottom
C333  22pF  [CAP0402_0-75]  17.17 71.27 0 top
C334  0.1uF  [CAP0402_0-75]  19.9 72.75 0 top
C335  0.01uF  [CAP0402_0-75]  22.02 74.95 270 top
C336  0.1uF  [CAP0402_0-75]  26 72.55 180 top
C337  2200pF  [CAP0402_0-75]  17.72 78.7 0 top
C338  10uF_10V  [CAPCT0805H_1]  13.63 77.77 270 top
C339  2200pF  [CAP0402_0-75]  33.26 66.43 180 bottom
C340  0.1uF  [CAP0402_0-75]  38.84 62.74 90 bottom
C341  0.1uF  [CAP0402_0-75]  36.46 62.74 90 bottom
C342  10uF  [CAP0805_1-5]  28.42 62.24 180 bottom
C343  3.3pF  [CAP0402_0-75]  21.48 61.08 180 bottom
C344  0.1uF  [CAP0402_0-75]  31.05 60.56 180 bottom
C345  22pF  [CAP0402_0-75]  33.91 59.09 180 bottom
C346  22uF  [CAP1206_2#2]  95.07 58.53 90 bottom
C347  2.2uF  [CAP0805_1-5]  18.69 58.44 180 bottom
C348  0.1uF  [CAP0402_0-75]  97.16 57.82 270 bottom
C349  0.1uF  [CAP0402_0-75]  25.09 57.45 0 bottom
C350  2.2uF  [CAP0805_1-5]  18.69 56.46 180 bottom
C351  2200pF  [CAP0402_0-75]  33.26 55.8 180 bottom
C352  0.1uF  [CAP0402_0-75]  19.25 54.74 180 bottom
C353  3.3pF  [CAP0402_0-75]  22.13 52.56 180 bottom
C354  10uF  [CAP0805_1-5]  28.42 52.39 180 bottom
C355  0.1uF  [CAP0402_0-75]  38.84 52.14 90 bottom
C356  0.1uF  [CAP0402_0-75]  36.46 52.14 90 bottom
C357  0.1uF  [CAP0402_0-75]  31.05 49.95 180 bottom
C358  22pF  [CAP0402_0-75]  33.91 48.46 180 bottom
C359  10uF_10V  [CAPCT0805H_1]  14.22 46.81 270 bottom
C360  680pF  [CAP0402_0-75]  21.99 42.45 270 bottom
C361  10uF  [CAP0805_1-5]  29.87 46.25 0 bottom
C362  3300pF  [CAP0402_0-75]  24.47 45.25 90 bottom
C363  680pF  [CAP0402_0-75]  21.83 45.25 90 bottom
C364  10uF  [CAP0805_1-5]  29.87 44.25 0 bottom
C365  0.1uF  [CAP0402_0-75]  16.65 40.36 180 bottom
C366  10uF_10V  [CAPCT0805H_1]  14.22 38.47 90 bottom
C367  680pF  [CAP0402_0-75]  19.32 38.43 180 bottom
C368  10uF  [CAP0805_1-5]  29.87 37.83 0 bottom
C369  0.1uF  [CAP0402_0-75]  46.75 42.93 0 bottom
C370  3300pF  [CAP0402_0-75]  24.47 36.83 90 bottom
C371  680pF  [CAP0402_0-75]  21.4 38.42 0 bottom
C372  10uF  [CAP0805_1-5]  29.87 35.83 0 bottom
C373  10uF_10V  [CAPCT0805H_1]  14.22 30.47 270 bottom
C374  680pF  [CAP0402_0-75]  21.96 26.13 270 bottom
C375  10uF  [CAP0805_1-5]  29.87 29.91 0 bottom
C376  3300pF  [CAP0402_0-75]  24.47 28.92 90 bottom
C377  680pF  [CAP0402_0-75]  21.83 28.92 90 bottom
C378  10uF  [CAP0805_1-5]  29.87 27.92 0 bottom
C379  0.1uF  [CAP0402_0-75]  16.52 24.03 180 bottom
C380  10uF_10V  [CAPCT0805H_1]  14.22 22.13 90 bottom
C381  680pF  [CAP0402_0-75]  19.32 22.1 180 bottom
C382  10uF  [CAP0805_1-5]  29.87 21.49 0 bottom
C383  3300pF  [CAP0402_0-75]  24.47 20.49 90 bottom
C384  680pF  [CAP0402_0-75]  21.59 22.06 0 bottom
C385  10uF  [CAP0805_1-5]  29.87 19.49 0 bottom
C765  0.1uF  [CAP0402_0-75]  39.04 40.13 180 bottom
C766  0.1uF  [CAP0402_0-75]  56.01 89.75 180 bottom
C767  0.1uF  [CAP0402_0-75]  16.92 87.03 0 top
C768  0.1uF  [CAP0402_0-75]  16.92 93.72 0 top
C769  0.1uF  [CAP0402_0-75]  16.92 93.72 0 bottom
C770  0.1uF  [CAP0402_0-75]  16.92 87.03 0 bottom
C771  0.1uF  [CAP0402_0-75]  16.92 60.79 0 bottom
C772  0.1uF  [CAP0402_0-75]  16.92 54.1 0 bottom
C773  0.1uF  [CAP0402_0-75]  16.92 54.1 0 top
C774  0.1uF  [CAP0402_0-75]  16.92 60.79 0 top
D1  ESD9X3.3ST5G  [DIO_SOD923_0-5]  90.62 188.31 0 bottom
D2  ESD9X3.3ST5G  [DIO_SOD923_0-5]  88.58 188.31 180 bottom
D3  SMCJ15CA  [DIO_SMC]  5.88 173.19 180 bottom
D4  SMCJ15CA  [DIO_SMC]  16.38 162.37 90 bottom
FL1  120E  [EMIFIL_BLM15A_0402_0-6]  66.55 191.8 0 top
FL2  120E  [EMIFIL_BLM15A_0402_0-6]  16.5 183.88 0 top
FL3  90E  [FILT4_MCZ1210DH_60X50_SMD_0-6]  14.58 181.98 180 top
FL4  120E  [EMIFIL_BLM15A_0402_0-6]  27.96 172.84 0 top
FL5  90E  [FILT4_MCZ1210DH_60X50_SMD_0-6]  21.16 160.95 180 top
FL6  120E  [EMIFIL_BLM15A_0402_0-6]  22.1 157.82 180 top
FL7  120E  [EMIFIL_BLM15A_0402_0-6]  41.9 123.98 0 top
FL8  120E  [EMIFIL_BLM15A_0402_0-6]  65.33 110.39 180 top
FL9  120E  [EMIFIL_BLM15A_0402_0-6]  64.95 103.13 180 top
FL10  120E  [EMIFIL_BLM15A_0402_0-6]  49.73 74.47 0 top
FL11  120E  [EMIFIL_BLM15A_0402_0-6]  60.77 52.37 180 top
FL12  120E  [EMIFIL_BLM15A_0402_0-6]  62.42 37.33 180 top
FL13  120E  [EMIFIL_BLM15A_0402_0-6]  99.35 188.55 90 bottom
FL14  120E  [EMIFIL_BLM15A_0402_0-6]  42.61 178.87 90 bottom
FL15  120E  [EMIFIL_BLM15A_0402_0-6]  74.4 176.15 90 bottom
FL16  90E  [FILT4_MCZ1210DH_60X50_SMD_0-6]  97 174.85 90 bottom
FL17  90E  [FILT4_MCZ1210DH_60X50_SMD_0-6]  95.07 174.85 90 bottom
FL18  90E  [FILT4_MCZ1210DH_60X50_SMD_0-6]  93.14 174.85 90 bottom
FL19  90E  [FILT4_MCZ1210DH_60X50_SMD_0-6]  91.2 174.85 90 bottom
FL20  120E  [EMIFIL_BLM15A_0402_0-6]  81.39 172.29 180 bottom
FL21  120E  [EMIFIL_BLM15A_0402_0-6]  81.02 170.42 90 bottom
FL22  120E  [EMIFIL_BLM15A_0402_0-6]  79.65 170.42 90 bottom
FL23  120E  [EMIFIL_BLM15A_0402_0-6]  39.17 164.89 270 bottom
FL24  120E  [EMIFIL_BLM15A_0402_0-6]  41.77 164.84 90 bottom
FL25  120E  [EMIFIL_BLM15A_0402_0-6]  37.68 144.49 0 bottom
J1  CON_PMC_2X60_M  [CON_PMC2X60_QTH-60-1-D-A_P_S_S_4-4]  88.22 111.76 90 top
J2  CON_PMC_2X60_M  [CON_PMC2X60_QTH-60-1-D-A_P_S_S_4-4]  88.22 62.38 90 top
J3  RECP_2X16  [RECPT_2X16_SSW-116-D-RA_R_T_5]  40.84 193.59 0 bottom
J4  CON_HDMI_1X19_F  [CON_19X1_10029449-001RLF_S_R_S_6-3]  92.1 196 0 bottom
J5  CON_JACK4_D4S20G-400A5  [CON_JACK4_D4S20G-400A5_P_R_T_10-6]  7.5 181.97 90 bottom
J6  CON_FLEX_1X36_52559-3652  [CON_FLEX1X36_52559-36_S_S_S_5-3]  62.82 182.58 180 bottom
J7  CON_JACK4_D4S20G-400A5  [CON_JACK4_D4S20G-400A5_P_R_T_10-6]  7.5 162.28 90 bottom
J8  CON_RCAJACK3_RCJ-022  [CON_RCAJACK3_RCJ-02X_S_S_T_16]  19.18 136.51 90 bottom
J9  CON_RCAJACK3_RCJ-022  [CON_RCAJACK3_RCJ-02X_S_S_T_16]  70.36 126.73 90 bottom
J10  HDR_1X8  [HDR_1X8_77311-818-08_S_T_8-6]  77.4 55.63 270 bottom
J11  CON_AUDIOJACK6_STX-4235  [CON_AV6_STX-4235-3-3_S_R_T_26]  3.48 129.31 90 bottom
J12  CON_AUDIOJACK6_STX-4235  [CON_AV6_STX-4235-3-3_S_R_T_26]  3.48 112.98 90 bottom
J13  CON_AUDIOJACK6_STX-4235  [CON_AV6_STX-4235-3-3_S_R_T_26]  3.48 96.64 90 bottom
J14  CON_PMC_2X20_F  [CON_PMC2X20_QSE-020-01-D-A_S_S_S_3-4]  63.72 83.45 0 bottom
J15  CON_AUDIOJACK6_STX-4235  [CON_AV6_STX-4235-3-3_S_R_T_26]  3.48 80.31 90 bottom
J16  CON_AUDIOJACK6_STX-4235  [CON_AV6_STX-4235-3-3_S_R_T_26]  3.48 63.97 90 bottom
J17  CON_PMC_2X60_F  [CON_PMC2X60_QSE-060-01-D-A_S_S_S_3-4]  89.13 52.97 270 bottom
J18  CON_AUDIOJACK6_STX-4235  [CON_AV6_STX-4235-3-3_S_R_T_26]  3.48 47.64 90 bottom
J19  CON_AUDIOJACK6_STX-4235  [CON_AV6_STX-4235-3-3_S_R_T_26]  3.48 31.3 90 bottom
J20  CON_PMC_2X20_F  [CON_PMC2X20_QSE-020-01-D-A_S_S_S_3-4]  63.73 22.49 0 bottom
L1  47uH  [INDP1210]  12.52 136.1 180 top
LD1  5988110107F  [LED_0805]  53.85 150.52 90 bottom
LD2  5988170107F  [LED_0805_0-7]  36.59 149.49 270 bottom
LD3  598-8140-107F  [LED_0805]  33.15 135.87 0 bottom
MOD1  PLR135/T10  [MOD5_PLR135T10]  8.92 139.91 270 bottom
NOREF  -  []  102.21 9 90 top
NOREF#2  -  [unnamed#2]  6.35 205 0 top
NOREF#3  -  [unnamed#2]  98.78 32.11 0 top
NOREF#4  -  [unnamed#2]  50.8 194.45 0 top
NOREF#5  -  [unnamed#2]  20.85 110.75 0 top
NOREF#6  -  []  -50.43 -35.3 0 top
NOREF#7  -  [unnamed#2]  14.55 187.97 0 top
NOREF#8  -  [unnamed#2]  90.78 3.5 0 top
NOREF#9  -  []  85.44 18.14 0 top
NOREF#10  -  [unnamed#2]  6.35 3.5 0 top
NOREF#11  -  []  -303.44 -89.85 0 top
NOREF#12  -  []  0 199.5 0 top
NOREF#13  -  [unnamed#2]  11.43 205 0 top
NOREF#14  -  [unnamed#3]  49.6 8 0 top
NOREF#15  -  [unnamed#2]  95.86 3.5 0 top
NOREF#16  -  [unnamed#3]  11.5 8 0 top
NOREF#17  -  []  886.01 768.92 0 top
NOREF#18  -  [unnamed#2]  11.43 3.5 0 top
NOREF#19  -  [unnamed#2]  94.03 13.75 0 top
NOREF#20  -  [unnamed#2]  90.78 205 0 top
NOREF#21  -  [unnamed#2]  74.8 194.45 0 top
NOREF#22  -  [unnamed#3]  49.59 200.5 180 top
NOREF#23  -  [unnamed#3]  87.69 200.5 180 top
NOREF#24  -  [unnamed#2]  14.55 13.75 0 top
NOREF#25  -  [unnamed#2]  5.08 152.33 0 top
NOREF#26  -  []  -302.17 -109.49 0 top
NOREF#27  -  [unnamed#2]  5.08 14.08 0 top
NOREF#28  -  [unnamed#3]  11.49 200.5 180 top
NOREF#29  -  [unnamed#2]  95.86 205 0 top
NOREF#30  -  [unnamed#2]  85.05 183.88 0 top
NOREF#31  -  []  102.21 0 90 top
NOREF#32  -  [unnamed#3]  87.7 8 0 top
NOREF#33  -  [unnamed#2]  11.43 205 180 bottom
NOREF#34  -  [unnamed#2]  11.43 3.5 180 bottom
NOREF#35  -  [unnamed#2]  14.55 187.97 180 bottom
NOREF#36  -  [unnamed#2]  94.03 13.75 180 bottom
NOREF#37  -  [unnamed#2]  14.55 13.75 180 bottom
NOREF#38  -  [unnamed#2]  90.78 3.5 180 bottom
NOREF#39  -  [unnamed#2]  90.78 205 180 bottom
Q1  BSS138-7-F  [SOT23-123_1-1]  51.27 149.72 0 bottom
Q2  BSS138-7-F  [SOT23-123_1-1]  39.6 149.44 90 bottom
Q3  BSS138-7-F  [SOT23-123_1-1]  33.15 138.99 180 bottom
R1  1K_1%  [RES0402_0-5#2]  58.12 195.36 270 top
R2  0E  [RES0402_0-5#2]  59.68 194.79 180 top
R3  0E  [RES0402_0-5#2]  59.68 193.62 180 top
R4  10K  [RES0402_0-5#2]  22.8 187.77 270 top
R5  10K  [RES0402_0-5#2]  24.08 187.77 270 top
R6  10K  [RES0402_0-5#2]  19.72 186.91 90 top
R7  10K  [RES0402_0-5#2]  20.95 186.91 90 top
R8  10K  [RES0402_0-5#2]  30.22 185.07 90 top
R10  1K_1%  [RES0402_0-5#2]  54.57 181.67 270 top
R11  10K  [RES0402_0-5#2]  55.57 181.67 90 top
R13  57.6K_1%  [RES0402_0-5]  13.64 179.23 270 top
R14  121K_1%  [RES0402_0-5]  13.64 177.31 270 top
R15  10K  [RES0402_0-5#2]  31.18 176.73 0 top
R16  61.9K_1%  [RES0402_0-5]  30.69 175.01 270 top
R17  107K_1%  [RES0402_0-5#2]  31.93 175.01 90 top
R18  33E_1%  [RES0402_0-5#2]  18.72 174.58 90 top
R19  33E_1%  [RES0402_0-5#2]  24.51 173.74 180 top
R20  30.9K_1%  [RES0402_0-5#2]  34.08 169.62 180 top
R21  510E_1%  [RES0402_0-5]  87.44 168.75 180 top
R22  820E_1%  [RES0402_0-5#2]  26.49 168.68 90 top
R23  1K_1%  [RES0402_0-5#2]  27.66 168.68 270 top
R24  95.3K_1%  [RES0402_0-5#2]  34.08 168.35 0 top
R25  10K  [RES0402_0-5#2]  77.81 167.07 180 top
R26  0E  [RES0402_0-5#2]  26.49 166.52 270 top
R27  0E  [RES0402_0-5#2]  27.66 166.52 270 top
R28  10K  [RES0402_0-5#2]  79.97 166.14 180 top
R29  10K  [RES0402_0-5#2]  97.91 166 180 top
R30  10K  [RES0402_0-5#2]  23.16 165.5 180 top
R31  22E_1%  [RES0402_0-5]  48.92 162.8 90 top
R32  10K  [RES0402_0-5#2]  76.85 164.88 90 top
R33  22E_1%  [RES0402_0-5]  52.39 164.73 90 top
R34  22E_1%  [RES0402_0-5]  53.63 164.73 90 top
R35  22E_1%  [RES0402_0-5]  54.88 164.73 90 top
R36  22E_1%  [RES0402_0-5]  56.12 164.73 90 top
R37  22E_1%  [RES0402_0-5]  57.37 164.73 90 top
R38  22E_1%  [RES0402_0-5]  58.61 164.73 90 top
R39  22E_1%  [RES0402_0-5]  59.86 164.73 90 top
R40  22E_1%  [RES0402_0-5]  61.1 164.73 90 top
R41  22E_1%  [RES0402_0-5]  63.2 164.45 90 top
R42  22E_1%  [RES0402_0-5]  64.36 164.45 90 top
R43  22E_1%  [RES0402_0-5]  67.92 163.89 90 top
R44  22E_1%  [RES0402_0-5]  72.64 163.89 90 top
R45  22E_1%  [RES0402_0-5]  70.26 163.89 90 top
R46  22E_1%  [RES0402_0-5]  71.42 163.89 90 top
R47  0E  [RES0402_0-5#2]  23.16 162.71 0 top
R48  10K  [RES0402_0-5#2]  79.71 162.58 180 top
R49  10K  [RES0402_0-5#2]  77.55 161.72 180 top
R50  0E  [RES0402_0-5#2]  44.55 161.68 90 top
R51  0E  [RES0402_0-5#2]  45.72 161.68 90 top
R52  10K  [RES0402_0-5#2]  79.71 160.85 180 top
R53  10K  [RES0402_0-5#2]  77.55 159.99 180 top
R54  4.7K  [RES0402_0-5#2]  39.56 159.7 90 top
R55  10K  [RES0402_0-5#2]  23.66 159.32 0 top
R56  4.7K  [RES0402_0-5#2]  40.69 159.2 90 top
R57  0E  [RES0402_0-5]  60.25 150.22 90 top
R58  0E  [RES0402_0-5#2]  90.04 157.91 90 top
R59  10K  [RES0402_0-5#2]  80.81 157.42 270 top
R60  0E  [RES0402_0-5]  57.61 150.22 90 top
R61  0E  [RES0402_0-5]  58.57 150.22 90 top
R62  68.1K_1%  [RES0402_0-5]  27.18 155.33 180 top
R63  22E_1%  [RES0402_0-5]  39.82 154.88 270 top
R64  4.7K  [RES0402_0-5#2]  32.03 154.57 90 top
R65  0E  [RES0402_0-5#2]  33.2 154.57 270 top
R66  0E  [RES0402_0-5#2]  34.37 154.57 270 top
R67  0E  [RES0402_0-5]  69.9 150.63 90 bottom
R68  4.7K  [RES0402_0-5#2]  44.07 154.17 0 top
R69  4.7K  [RES0402_0-5#2]  46.21 154.17 180 top
R70  40.2K_1%  [RES0402_0-5#2]  27.18 154.12 0 top
R71  10K  [RES0402_0-5#2]  13.47 152.14 90 top
R72  0E  [RES0402_0-5]  71.78 148.14 90 bottom
R73  0E  [RES0402_0-5]  72.75 148.14 90 bottom
R74  0E  [RES0402_0-5]  73.76 148.14 90 bottom
R75  0E  [RES0402_0-5]  75.23 148.14 90 bottom
R76  0E  [RES0402_0-5]  76.25 148.14 90 bottom
R77  0E  [RES0402_0-5]  77.27 148.14 90 bottom
R78  0E  [RES0402_0-5]  78.28 148.14 90 bottom
R79  0E  [RES0402_0-5]  79.3 148.14 90 bottom
R80  0E  [RES0402_0-5]  80.77 148.19 90 bottom
R81  0E  [RES0402_0-5]  81.79 148.19 90 bottom
R82  0E  [RES0402_0-5]  82.8 148.19 90 bottom
R83  0E  [RES0402_0-5]  83.82 148.19 90 bottom
R84  0E  [RES0402_0-5]  87.22 148.16 90 bottom
R85  0E  [RES0402_0-5]  88.22 148.16 90 bottom
R86  0E  [RES0402_0-5]  89.22 148.16 90 bottom
R87  0E  [RES0402_0-5]  90.72 148.16 90 bottom
R88  0E  [RES0402_0-5]  91.72 148.16 90 bottom
R89  0E  [RES0402_0-5]  92.72 148.16 90 bottom
R90  0E  [RES0402_0-5]  93.72 148.16 90 bottom
R91  0E  [RES0402_0-5]  94.72 148.16 90 bottom
R92  0E  [RES0402_0-5]  96.22 148.16 90 bottom
R93  0E  [RES0402_0-5]  97.22 148.16 90 bottom
R94  0E  [RES0402_0-5]  98.22 148.16 90 bottom
R95  0E  [RES0402_0-5]  99.22 148.16 90 bottom
R96  10K  [RES0402_0-5#2]  42.19 147.11 180 top
R97  10K  [RES0402_0-5#2]  42.19 145.97 180 top
R98  10K  [RES0402_0-5#2]  44.42 143.03 270 top
R99  2.2K  [RES0402_0-5#2]  25.27 141.31 90 top
R100  47K  [RES0402_0-5#2]  24.13 138.9 270 top
R101  680E_1%  [RES0603_0-75]  39.65 136.04 180 top
R102  75E  [RES0402_0-5]  23.32 135.59 270 top
R103  10K  [RES0402_0-5]  64.01 131.55 270 top
R104  0E  [RES0402_0-5#2]  76.11 131.39 90 top
R105  10K  [RES0402_0-5#2]  22.32 130.9 180 top
R106  4.75K_1%  [RES0402_0-5#2]  23.98 123.48 180 top
R107  360E_1%  [RES0402_0-5]  23.98 124.72 0 top
R108  10K  [RES0402_0-5#2]  22.32 129.74 0 top
R109  47.5E_1%  [RES0402_0-5#2]  16.36 129.63 180 top
R110  0E  [RES0402_0-5#2]  63.95 128.88 180 top
R111  1.5K_1%  [RES0402_0-5#2]  22.32 128.57 180 top
R112  110E_1%  [RES0402_0-5#2]  75.62 127.69 180 top
R113  7.5K  [RES0402_0-5]  27.29 127.55 180 top
R114  360E_1%  [RES0402_0-5]  23 126.93 90 top
R115  3.74K_1%  [RES0402_0-5#2]  25.64 126.93 90 top
R116  0E  [RES0402_0-5#2]  73.32 126.73 180 top
R117  7.5K  [RES0402_0-5]  27.3 126.31 180 top
R118  47K_1%  [RES0402_0-5]  14.22 125.86 270 top
R119  220E_1%  [RES0402_0-5#2]  76.11 126.02 90 top
R120  10K  [RES0402_0-5#2]  47.52 125.05 90 top
R121  33E_1%  [RES0402_0-5#2]  48.77 125.05 90 top
R122  33E_1%  [RES0402_0-5#2]  50.01 125.05 90 top
R123  33E_1%  [RES0402_0-5#2]  51.26 125.05 90 top
R124  33E_1%  [RES0402_0-5#2]  52.5 125.05 90 top
R125  33E_1%  [RES0402_0-5#2]  53.75 125.05 90 top
R126  33E_1%  [RES0402_0-5#2]  54.99 125.05 90 top
R127  10K  [RES0402_0-5#2]  24.96 121.71 180 top
R128  47K_1%  [RES0402_0-5]  14.22 122.77 90 top
R129  10K  [RES0402_0-5#2]  24.96 120.54 0 top
R130  10K  [RES0402_0-5]  71.76 121.33 180 top
R131  1.5K_1%  [RES0402_0-5#2]  23.3 119.48 90 top
R132  7.5K  [RES0402_0-5]  27.3 119.12 180 top
R133  47.5E_1%  [RES0402_0-5#2]  16.36 118.99 180 top
R134  360E_1%  [RES0402_0-5]  21.7 118.93 0 top
R135  3.74K_1%  [RES0402_0-5#2]  25.64 118.5 90 top
R136  4.75K_1%  [RES0402_0-5#2]  18.05 118.5 90 top
R137  360E_1%  [RES0402_0-5]  19.28 118.5 270 top
R138  7.5K  [RES0402_0-5]  27.3 117.89 180 top
R139  10K  [RES0402_0-5#2]  29.37 115.16 180 top
R140  4.75K_1%  [RES0402_0-5#2]  31.03 107.64 180 top
R141  360E_1%  [RES0402_0-5]  31.03 108.87 0 top
R142  10K  [RES0402_0-5#2]  29.37 114 0 top
R143  47.5E_1%  [RES0402_0-5#2]  16.36 113.07 180 top
R144  0E  [RES0402_0-5]  93.11 114.59 90 top
R145  1.5K_1%  [RES0402_0-5#2]  29.37 112.83 180 top
R146  0E  [RES0402_0-5]  93.11 112.94 270 top
R147  7.5K  [RES0402_0-5]  34.34 111.8 180 top
R148  360E_1%  [RES0402_0-5]  30.05 111.19 90 top
R149  3.74K_1%  [RES0402_0-5#2]  32.69 111.19 90 top
R150  7.5K  [RES0402_0-5]  34.35 110.57 180 top
R151  47K_1%  [RES0402_0-5]  14.22 109.3 270 top
R152  0E  [RES0402_0-5#2]  68.17 108.89 0 top
R153  10K  [RES0402_0-5#2]  31.6 106.4 180 top
R154  22E_1%  [RES0402_0-5]  63.35 108 0 top
R155  47K_1%  [RES0402_0-5]  14.22 106.2 90 top
R156  10K  [RES0402_0-5#2]  31.6 105.23 0 top
R157  22E_1%  [RES0402_0-5]  63.35 106.88 0 top
R158  10K  [RES0402_0-5#2]  41.58 107.57 270 top
R159  10K  [RES0402_0-5#2]  42.8 107.57 90 top
R160  1.5K_1%  [RES0402_0-5#2]  31.11 103.59 90 top
R161  22E_1%  [RES0402_0-5]  63.35 105.76 0 top
R162  7.5K  [RES0402_0-5]  35.11 103.23 180 top
R163  360E_1%  [RES0402_0-5]  29.48 102.98 0 top
R164  3.74K_1%  [RES0402_0-5#2]  33.45 102.61 90 top
R165  47.5E_1%  [RES0402_0-5#2]  16.36 102.43 180 top
R166  10K  [RES0402_0-5#2]  41.58 105.4 90 top
R167  10K  [RES0402_0-5#2]  42.8 105.4 270 top
R168  4.75K_1%  [RES0402_0-5#2]  25.1 102.61 90 top
R169  360E_1%  [RES0402_0-5]  26.33 102.61 270 top
R170  7.5K  [RES0402_0-5]  35.11 102 180 top
R171  220K  [RES0402_0-5]  44.13 103.39 0 top
R172  47E  [RES0402_0-5]  33.91 100.51 0 top
R173  1.5K  [RES0402_0-5#2]  35.48 99.9 90 top
R174  0E  [RES0402_0-5#2]  44.13 102.2 0 top
R175  49.9E_1%  [RES0402_0-5#2]  22.13 96.41 0 top
R176  100K  [RES0402_0-5]  24 95.92 90 top
R177  0E  [RES0402_0-5#2]  25.09 95.92 270 top
R178  0E  [RES0402_0-5#2]  26.16 95.92 270 top
R179  1.5K  [RES0402_0-5#2]  37.65 95.68 90 top
R180  3K  [RES0402_0-5#2]  31.05 95.43 0 top
R181  150K_1%  [RES0402_0-5#2]  22.13 94.12 180 top
R182  5.9K_1%  [RES0402_0-5#2]  16.46 91.85 270 top
R183  10K  [RES0402_0-5#2]  64.41 97.67 90 bottom
R184  1.5K  [RES0402_0-5#2]  34.96 91.48 270 top
R185  0E  [RES0402_0-5#2]  14.8 91.36 0 top
R186  47E  [RES0402_0-5]  33.26 90.88 0 top
R187  22E_1%  [RES0402_0-5]  65.41 97.67 90 bottom
R188  22E_1%  [RES0402_0-5]  65.41 91.06 270 bottom
R189  47E  [RES0402_0-5]  33.91 89.87 0 top
R190  0E  [RES0402_0-5#2]  14.8 89.38 0 top
R191  1.5K  [RES0402_0-5#2]  35.68 89.3 90 top
R192  5.9K_1%  [RES0402_0-5#2]  16.46 88.89 90 top
R193  150K_1%  [RES0402_0-5#2]  21.48 85.65 180 top
R194  3K  [RES0402_0-5#2]  31.05 85.58 0 top
R195  100K  [RES0402_0-5]  24 85.09 270 top
R196  0E  [RES0402_0-5#2]  25.09 85.09 90 top
R197  0E  [RES0402_0-5#2]  26.16 85.09 90 top
R198  1.5K  [RES0402_0-5#2]  37.65 85.08 90 top
R199  49.9E_1%  [RES0402_0-5#2]  21.48 84.6 0 top
R200  3K  [RES0402_0-5#2]  27.9 77.01 90 top
R201  1.5K  [RES0402_0-5#2]  29.59 77.5 0 top
R202  47E  [RES0402_0-5]  31.31 76.93 90 top
R203  1.5K  [RES0402_0-5#2]  34.96 80.83 270 top
R204  47E  [RES0402_0-5]  33.26 80.22 0 top
R205  1.5K  [RES0402_0-5#2]  32.88 72.55 90 top
R206  10K  [RES0402_0-5]  82.68 77.39 0 top
R207  47E  [RES0402_0-5]  30.76 68.23 270 top
R208  10K  [RES0402_0-5]  82.68 76.37 0 top
R209  1.5K  [RES0402_0-5#2]  29.04 67.6 0 top
R210  3K  [RES0402_0-5#2]  26 73.15 0 bottom
R211  1.5K  [RES0402_0-5#2]  30.05 76.93 90 bottom
R212  47E  [RES0402_0-5]  28.33 77.5 0 bottom
R213  10K  [RES0402_0-5#2]  62.83 73.16 90 bottom
R214  22E_1%  [RES0402_0-5]  63.95 73.16 90 bottom
R215  22E_1%  [RES0402_0-5]  63.95 66.55 270 bottom
R216  0E  [RES0402_0-5#2]  81.8 70.38 0 top
R217  1.5K  [RES0402_0-5#2]  31.67 72.55 90 bottom
R218  0E  [RES0402_0-5#2]  81.8 69.16 0 top
R219  47E  [RES0402_0-5]  33.91 67.53 0 top
R220  1.5K  [RES0402_0-5#2]  35.61 66.92 90 top
R221  47E  [RES0402_0-5]  28.98 67.6 0 bottom
R222  1.5K  [RES0402_0-5#2]  30.7 68.23 270 bottom
R223  49.9E_1%  [RES0402_0-5#2]  22.13 63.22 0 top
R224  1.5K  [RES0402_0-5#2]  37.65 62.74 90 top
R225  100K  [RES0402_0-5]  24.05 62.73 90 top
R226  0E  [RES0402_0-5#2]  25.09 62.73 270 top
R227  0E  [RES0402_0-5#2]  26.26 62.73 270 top
R228  3K  [RES0402_0-5#2]  31.05 62.24 0 top
R229  150K_1%  [RES0402_0-5#2]  22.13 61.06 180 top
R230  5.9K_1%  [RES0402_0-5#2]  16.46 58.93 270 top
R231  1.5K  [RES0402_0-5#2]  35.03 58.52 270 top
R232  0E  [RES0402_0-5#2]  14.8 58.44 0 top
R233  0E  [RES0402_0-5#2]  95.21 66.78 270 bottom
R234  47E  [RES0402_0-5]  33.26 57.95 0 top
R235  0E  [RES0402_0-5#2]  96.37 66.81 270 bottom
R236  47E  [RES0402_0-5]  33.91 56.77 0 top
R237  0E  [RES0402_0-5#2]  14.8 56.46 0 top
R238  1.5K  [RES0402_0-5#2]  35.61 56.21 90 top
R239  5.9K_1%  [RES0402_0-5#2]  16.46 55.97 90 top
R240  150K_1%  [RES0402_0-5#2]  21.48 52.56 180 top
R241  3K  [RES0402_0-5#2]  31.05 52.39 0 top
R242  1.5K  [RES0402_0-5#2]  37.65 52.14 90 top
R243  100K  [RES0402_0-5]  24.05 51.9 270 top
R244  0E  [RES0402_0-5#2]  25.09 51.9 90 top
R245  0E  [RES0402_0-5#2]  26.26 51.9 90 top
R246  10K  [RES0402_0-5#2]  79.38 51.64 180 top
R247  49.9E_1%  [RES0402_0-5#2]  21.48 51.41 0 top
R248  10K  [RES0402_0-5#2]  69.44 50.37 0 top
R249  10K  [RES0402_0-5#2]  79.39 50.37 180 top
R250  10K  [RES0402_0-5#2]  22.32 49.23 180 top
R251  10K  [RES0402_0-5#2]  79.37 49.1 180 top
R252  5.6K_1%  [RES0402_0-5#2]  23.98 41.84 180 top
R253  360E_1%  [RES0402_0-5]  23.98 43.07 0 top
R254  10K  [RES0402_0-5#2]  22.32 48.06 0 top
R255  47.5E_1%  [RES0402_0-5#2]  16.36 47.96 180 top
R256  1.5K  [RES0402_0-5#2]  35.03 47.92 270 top
R257  47E  [RES0402_0-5]  33.26 47.32 0 top
R258  1.5K_1%  [RES0402_0-5#2]  22.32 46.89 180 top
R259  7.5K  [RES0402_0-5]  27.29 45.87 180 top
R260  0E  [RES0603_0-75]  94.11 45.32 180 top
R261  360E_1%  [RES0402_0-5]  23 45.25 90 top
R262  3.74K_1%  [RES0402_0-5#2]  25.64 45.25 90 top
R263  0E  [RES0402_0-5#2]  59.49 50.07 270 top
R264  220K  [RES0402_0-5]  60.69 50.07 270 top
R265  7.5K  [RES0402_0-5]  27.3 44.63 180 top
R266  47K_1%  [RES0402_0-5]  14.22 44.18 270 top
R267  0E  [RES0402_0-5#2]  64.63 47.43 0 top
R268  10K  [RES0402_0-5#2]  22.38 40.77 180 top
R269  47K_1%  [RES0402_0-5]  14.22 41.09 90 top
R270  22E_1%  [RES0402_0-5]  43.36 45.55 180 top
R271  10K  [RES0402_0-5#2]  62.67 45.34 90 top
R272  10K  [RES0402_0-5#2]  63.94 45.34 270 top
R273  10K  [RES0402_0-5#2]  22.38 39.6 0 top
R274  22E_1%  [RES0402_0-5]  43.36 44.43 180 top
R275  1.5K_1%  [RES0402_0-5#2]  23.26 37.81 90 top
R276  22E_1%  [RES0402_0-5]  43.36 43.31 180 top
R277  10K  [RES0402_0-5#2]  62.64 43.19 270 top
R278  10K  [RES0402_0-5#2]  63.91 43.19 90 top
R279  7.5K  [RES0402_0-5]  27.3 37.44 180 top
R280  47.5E_1%  [RES0402_0-5#2]  16.36 37.32 180 top
R281  360E_1%  [RES0402_0-5]  21.4 37.19 0 top
R282  3.74K_1%  [RES0402_0-5#2]  25.64 36.83 90 top
R283  5.6K_1%  [RES0402_0-5#2]  18.05 36.83 90 top
R284  360E_1%  [RES0402_0-5]  19.28 36.83 270 top
R285  7.5K  [RES0402_0-5]  27.3 36.21 180 top
R286  10K  [RES0402_0-5#2]  22.32 32.89 180 top
R287  5.6K_1%  [RES0402_0-5#2]  23.98 25.52 180 top
R288  360E_1%  [RES0402_0-5]  23.98 26.75 0 top
R289  10K  [RES0402_0-5#2]  22.32 31.72 0 top
R290  47.5E_1%  [RES0402_0-5#2]  16.36 31.62 180 top
R291  1.5K_1%  [RES0402_0-5#2]  22.32 30.56 180 top
R292  7.5K  [RES0402_0-5]  27.29 29.53 180 top
R293  360E_1%  [RES0402_0-5]  23 28.92 90 top
R294  3.74K_1%  [RES0402_0-5#2]  25.64 28.92 90 top
R295  7.5K  [RES0402_0-5]  27.3 28.3 180 top
R296  47K_1%  [RES0402_0-5]  14.22 27.93 270 top
R297  4.7K  [RES0402_0-5#2]  60.93 25.5 270 top
R298  4.7K  [RES0402_0-5#2]  64.13 25.5 90 top
R299  10K  [RES0402_0-5#2]  23.76 24.26 180 top
R300  47K_1%  [RES0402_0-5]  14.22 24.68 90 top
R301  10K  [RES0402_0-5#2]  23.76 23.09 0 top
R302  1.5K_1%  [RES0402_0-5#2]  23.27 21.47 90 top
R303  7.5K  [RES0402_0-5]  27.3 21.11 180 top
R304  47.5E_1%  [RES0402_0-5#2]  16.36 20.98 180 top
R305  360E_1%  [RES0402_0-5]  21.59 20.89 0 top
R306  3.74K_1%  [RES0402_0-5#2]  25.64 20.49 90 top
R307  5.6K_1%  [RES0402_0-5#2]  18.05 20.49 90 top
R308  360E_1%  [RES0402_0-5]  19.28 20.42 270 top
R309  7.5K  [RES0402_0-5]  27.3 19.88 180 top
R310  4.7K  [RES0402_0-5#2]  64.13 19.48 270 top
R311  10K  [RES0402_0-5#2]  41.33 188.53 0 bottom
R312  22E_1%  [RES0402_0-5]  22.26 187.9 180 bottom
R313  10K  [RES0402_0-5#2]  41.33 187.28 180 bottom
R314  10K  [RES0402_0-5#2]  37.65 186.5 90 bottom
R315  22E_1%  [RES0402_0-5]  36.35 186.46 90 bottom
R316  4.7K  [RES0402_0-5#2]  48.52 186.28 180 bottom
R317  4.7K  [RES0402_0-5#2]  46.38 186.28 0 bottom
R318  0E  [RES0402_0-5#2]  40.84 185.58 270 bottom
R319  10K  [RES0402_0-5#2]  79.66 183.57 180 bottom
R320  10K  [RES0402_0-5#2]  77.6 183.57 0 bottom
R321  10K  [RES0402_0-5#2]  39.01 181.93 90 bottom
R322  10K  [RES0402_0-5#2]  86.08 177.61 270 top
R323  22E_1%  [RES0402_0-5]  36.24 179.45 270 bottom
R324  22E_1%  [RES0402_0-5]  67.57 179.06 90 bottom
R325  4.7K  [RES0402_0-5#2]  46.48 178.72 90 bottom
R326  10K  [RES0402_0-5#2]  40.81 178.72 270 bottom
R327  4.7K  [RES0402_0-5#2]  82.34 178.48 0 bottom
R328  10K  [RES0402_0-5#2]  94.75 180.19 90 top
R329  4.7K  [RES0402_0-5#2]  20.72 177.1 0 bottom
R330  4.7K  [RES0402_0-5#2]  22.9 169.84 0 bottom
R331  10K  [RES0402_0-5#2]  13.61 169.09 270 bottom
R332  1.87K_1%  [RES0402_0-5#2]  22.89 168.67 0 bottom
R333  10K  [RES0402_0-5#2]  77.81 167.07 0 bottom
R334  10K  [RES0402_0-5#2]  79.97 166.14 0 bottom
R335  10K  [RES0402_0-5#2]  97.91 166 0 bottom
R336  10K  [RES0402_0-5#2]  23.16 165.5 180 bottom
R337  10K  [RES0402_0-5#2]  76.85 164.88 270 bottom
R338  10K  [RES0402_0-5#2]  79.97 164.37 180 bottom
R339  4.7K  [RES0402_0-5#2]  37.4 163.38 0 bottom
R340  10K  [RES0402_0-5#2]  77.55 163.12 0 bottom
R341  10K  [RES0402_0-5#2]  79.71 162.58 0 bottom
R342  4.7K  [RES0402_0-5#2]  37.4 162.22 180 bottom
R343  10K  [RES0402_0-5#2]  77.55 161.72 0 bottom
R344  10K  [RES0402_0-5#2]  79.71 160.85 0 bottom
R345  10K  [RES0402_0-5#2]  77.55 159.99 0 bottom
R346  0E  [RES0402_0-5#2]  80.81 157.42 270 bottom
R347  0E  [RES0402_0-5#2]  71.39 154.53 180 bottom
R348  10K  [RES0402_0-5#2]  71.02 151.65 270 bottom
R349  4.7K  [RES0402_0-5#2]  22.4 150.99 0 bottom
R350  100E  [RES0402_0-5]  53.43 152.67 0 bottom
R351  10K  [RES0402_0-5#2]  44.23 150.05 270 bottom
R352  10K  [RES0402_0-5#2]  42.98 150.05 90 bottom
R353  1.87K_1%  [RES0402_0-5#2]  22.4 149.72 0 bottom
R354  10K  [RES0402_0-5#2]  67.24 148.78 180 bottom
R355  0E  [RES0402_0-5#2]  42.49 148.39 0 bottom
R356  10K  [RES0402_0-5#2]  70.29 148.41 180 bottom
R357  10K  [RES0402_0-5#2]  39.45 147.11 180 bottom
R358  50E_1%  [RES0402_0-75]  36.59 146.84 90 bottom
R359  330E_1%  [RES0402_0-5#2]  55.58 145.98 90 bottom
R360  10K  [RES0402_0-5#2]  39.45 145.97 180 bottom
R361  10K  [RES0402_0-5#2]  41.61 140.99 180 bottom
R362  10K  [RES0402_0-5#2]  70.29 140.66 0 bottom
R363  10K  [RES0402_0-5#2]  53.37 137.34 0 bottom
R364  10K  [RES0402_0-5#2]  51.3 137.21 180 bottom
R365  10K  [RES0402_0-5#2]  53.37 136.1 180 bottom
R366  10K  [RES0402_0-5#2]  51.3 136.1 0 bottom
R367  100E  [RES0402_0-5]  33.53 134.02 0 bottom
R368  10K  [RES0402_0-5#2]  22.32 130.9 180 bottom
R369  360E_1%  [RES0402_0-5]  23.98 124.72 0 bottom
R370  4.75K_1%  [RES0402_0-5#2]  23.98 123.48 180 bottom
R371  10K  [RES0402_0-5#2]  22.32 129.74 0 bottom
R372  47.5E_1%  [RES0402_0-5#2]  16.36 129.63 180 bottom
R373  1.5K_1%  [RES0402_0-5#2]  22.32 128.57 180 bottom
R374  10K  [RES0402_0-5#2]  82.37 128.33 0 bottom
R375  7.5K  [RES0402_0-5]  27.29 127.55 180 bottom
R376  10K  [RES0402_0-5#2]  82.37 127.19 0 bottom
R377  3.74K_1%  [RES0402_0-5#2]  25.64 126.93 90 bottom
R378  360E_1%  [RES0402_0-5]  23 126.93 90 bottom
R379  7.5K  [RES0402_0-5]  27.3 126.31 180 bottom
R380  47K_1%  [RES0402_0-5]  14.22 125.86 270 bottom
R381  10K  [RES0402_0-5#2]  24.96 121.71 180 bottom
R382  47K_1%  [RES0402_0-5]  14.22 122.77 90 bottom
R383  10K  [RES0402_0-5#2]  24.96 120.54 0 bottom
R384  1.5K_1%  [RES0402_0-5#2]  23.3 119.48 90 bottom
R385  7.5K  [RES0402_0-5]  27.3 119.12 180 bottom
R386  47.5E_1%  [RES0402_0-5#2]  16.36 118.99 180 bottom
R387  3.74K_1%  [RES0402_0-5]  25.64 118.5 90 bottom
R388  360E_1%  [RES0402_0-5]  21.7 118.93 0 bottom
R389  360E_1%  [RES0402_0-5]  19.93 118.5 270 bottom
R390  4.75K_1%  [RES0402_0-5#2]  18.7 118.5 90 bottom
R391  7.5K  [RES0402_0-5]  27.3 117.89 180 bottom
R392  10K  [RES0402_0-5#2]  29.37 115.16 180 bottom
R393  10K  [RES0402_0-5#2]  86.41 111.41 180 bottom
R394  10K  [RES0402_0-5#2]  84.38 111.41 0 bottom
R395  360E_1%  [RES0402_0-5]  31.03 108.87 0 bottom
R396  4.75K_1%  [RES0402_0-5#2]  31.03 107.64 180 bottom
R397  10K  [RES0402_0-5#2]  29.37 114 0 bottom
R398  47.5E_1%  [RES0402_0-5#2]  16.36 113.07 180 bottom
R399  1.5K_1%  [RES0402_0-5#2]  29.37 112.83 180 bottom
R400  7.5K  [RES0402_0-5]  34.34 111.8 180 bottom
R401  3.74K_1%  [RES0402_0-5#2]  32.69 111.19 90 bottom
